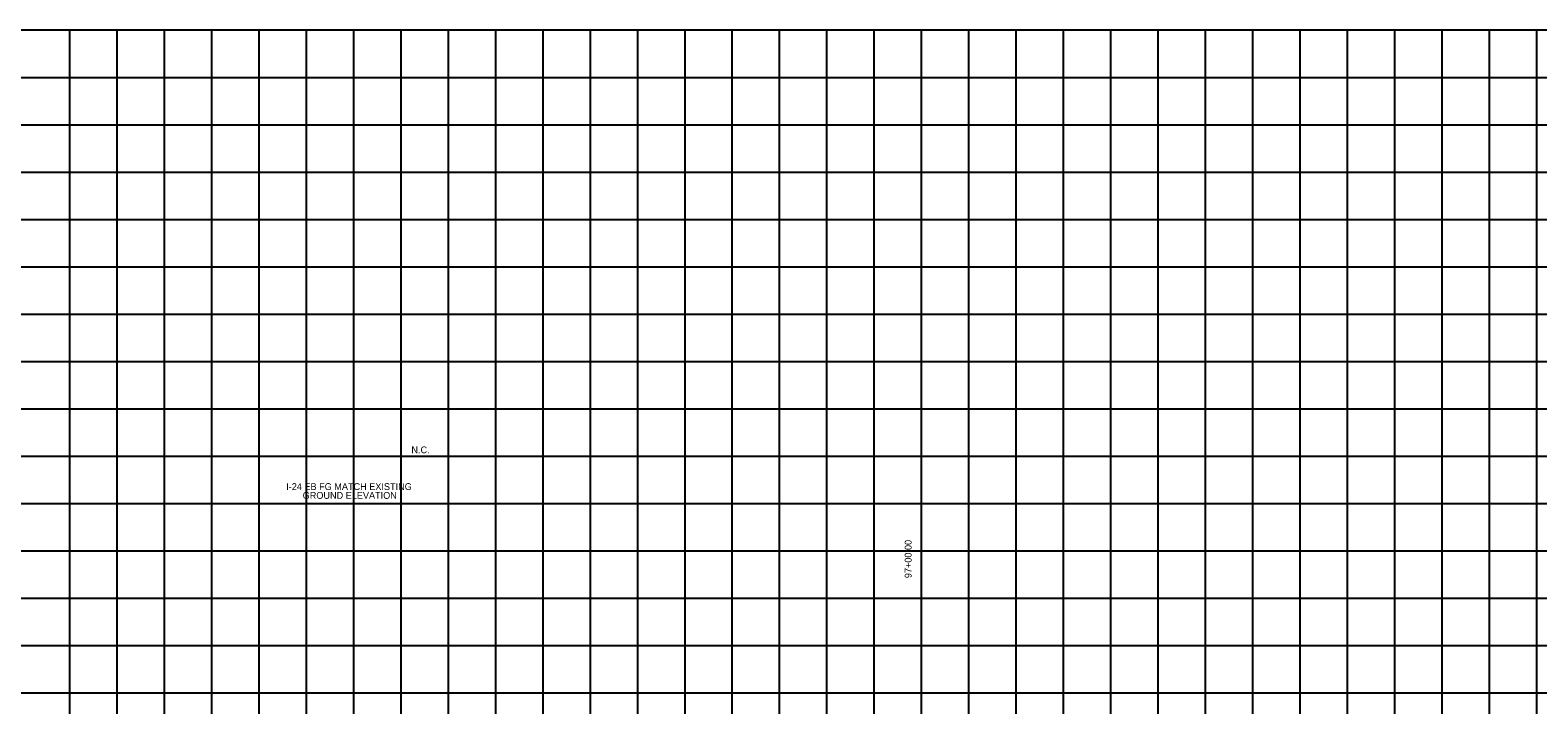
# Model space of a CAD drawing. Extents: x -7164 to 2214450, y -19642 to 253469.
# Drawn here: x 2758 to 4351, y -1713 to -1000 of the extents above; entities that cross this region are included whole.
import ezdxf

# ---------------------------------------------------------------- set-up
doc = ezdxf.new("R2010")
doc.units = 0
for name, color, linetype in [('DESIGN - PROFILE - Proposed Curve Text', 7, 'Continuous'), ('DESIGN - SCRATCH - User 1', 7, 'Continuous'), ('DESIGN - SHEET - Light Grid', 7, 'Continuous')]:
    doc.layers.add(name, color=color, linetype=linetype)

msp = doc.modelspace()

# ---------------------------------------------------------------- linework, layer by layer
at = {"layer": 'DESIGN - PROFILE - Proposed Curve Text'}
for p, q in [((2592.8, -1450), (3787.9, -1450)), ((2592.8, -1450), (3800, -1450)), ((2592.8, -1450), (3787.9, -1450)), ((2592.8, -1450), (3800, -1450)), ((3700, -1600), (3700, -1481.9)), ((3700, -1600), (3700, -1481.9)), ((2500, -1500), (3700, -1500)), ((2500, -1500), (3700, -1500))]:
    msp.add_line(p, q, dxfattribs=at)
at = {"layer": 'DESIGN - SCRATCH - User 1'}
msp.add_line((12400, -1000), (0, -1000), dxfattribs=at)
msp.add_line((12400, -1000), (0, -1000), dxfattribs=at)
at = {"layer": 'DESIGN - SHEET - Light Grid'}
for p, q in [((2800, -3000), (2800, -1000)), ((2800, -3000), (2800, -1000)), ((2850, -3000), (2850, -1000)), ((2850, -3000), (2850, -1000)), ((2900, -3000), (2900, -1000)), ((2900, -3000), (2900, -1000)), ((2950, -3000), (2950, -1000)), ((2950, -3000), (2950, -1000)), ((3000, -3000), (3000, -1000)), ((3000, -3000), (3000, -1000)), ((3050, -3000), (3050, -1000)), ((3050, -3000), (3050, -1000)), ((3100, -3000), (3100, -1000)), ((3100, -3000), (3100, -1000)), ((3150, -3000), (3150, -1000)), ((3150, -3000), (3150, -1000)), ((3200, -3000), (3200, -1000)), ((3200, -3000), (3200, -1000)), ((3250, -3000), (3250, -1000)), ((3250, -3000), (3250, -1000)), ((3300, -3000), (3300, -1000)), ((3300, -3000), (3300, -1000)), ((3350, -3000), (3350, -1000)), ((3350, -3000), (3350, -1000)), ((3400, -3000), (3400, -1000)), ((3400, -3000), (3400, -1000)), ((3450, -3000), (3450, -1000)), ((3450, -3000), (3450, -1000)), ((3500, -3000), (3500, -1000)), ((3500, -3000), (3500, -1000)), ((3550, -3000), (3550, -1000)), ((3550, -3000), (3550, -1000)), ((3600, -3000), (3600, -1000)), ((3600, -3000), (3600, -1000)), ((3650, -3000), (3650, -1000)), ((3650, -3000), (3650, -1000)), ((3700, -3000), (3700, -1000)), ((3700, -3000), (3700, -1000)), ((3750, -3000), (3750, -1000)), ((3750, -3000), (3750, -1000)), ((3800, -3000), (3800, -1000)), ((3800, -3000), (3800, -1000)), ((3850, -3000), (3850, -1000)), ((3850, -3000), (3850, -1000)), ((3900, -3000), (3900, -1000)), ((3900, -3000), (3900, -1000)), ((3950, -3000), (3950, -1000)), ((3950, -3000), (3950, -1000)), ((4000, -3000), (4000, -1000)), ((4000, -3000), (4000, -1000)), ((4050, -3000), (4050, -1000)), ((4050, -3000), (4050, -1000)), ((4100, -3000), (4100, -1000)), ((4100, -3000), (4100, -1000)), ((4150, -3000), (4150, -1000)), ((4150, -3000), (4150, -1000)), ((4200, -3000), (4200, -1000)), ((4200, -3000), (4200, -1000)), ((4250, -3000), (4250, -1000)), ((4250, -3000), (4250, -1000)), ((4300, -3000), (4300, -1000)), ((4300, -3000), (4300, -1000)), ((4350, -3000), (4350, -1000)), ((4350, -3000), (4350, -1000)), ((0, -1050), (12400, -1050)), ((0, -1050), (12400, -1050)), ((0, -1100), (12400, -1100)), ((0, -1100), (12400, -1100)), ((0, -1150), (12400, -1150)), ((0, -1150), (12400, -1150)), ((0, -1200), (12400, -1200)), ((0, -1200), (12400, -1200)), ((0, -1250), (12400, -1250)), ((0, -1250), (12400, -1250)), ((0, -1300), (12400, -1300)), ((0, -1300), (12400, -1300)), ((0, -1350), (12400, -1350)), ((0, -1350), (12400, -1350)), ((0, -1400), (12400, -1400)), ((0, -1400), (12400, -1400)), ((0, -1450), (12400, -1450)), ((0, -1450), (12400, -1450)), ((0, -1500), (12400, -1500)), ((0, -1500), (12400, -1500)), ((0, -1550), (12400, -1550)), ((0, -1550), (12400, -1550)), ((0, -1600), (12400, -1600)), ((0, -1600), (12400, -1600)), ((0, -1650), (12400, -1650)), ((0, -1650), (12400, -1650)), ((0, -1700), (12400, -1700)), ((0, -1700), (12400, -1700))]:
    msp.add_line(p, q, dxfattribs=at)

# ---------------------------------------------------------------- texts
at = {"layer": 'DESIGN - PROFILE - Proposed Curve Text'}
for s, p in [('N.C.', (3160.9, -1446.9)), ('I-24 EB FG MATCH EXISTING', (3028.6, -1485.7)), ('GROUND ELEVATION ', (3046, -1495))]:
    msp.add_text(s, height=7.2, dxfattribs=at).set_placement(p)
for s, rotation, p in [('N.C.', 360, (3160.9, -1446.9)), ('I-24 EB FG MATCH EXISTING', 360, (3028.6, -1485.7)), ('GROUND ELEVATION ', 360, (3046, -1495)), ('97+00.00', 90, (3689.4, -1578.8)), ('97+00.00', 90, (3689.4, -1578.8))]:
    msp.add_text(s, height=7.2, rotation=rotation, dxfattribs=at).set_placement(p)

doc.saveas('drawing.dxf')
